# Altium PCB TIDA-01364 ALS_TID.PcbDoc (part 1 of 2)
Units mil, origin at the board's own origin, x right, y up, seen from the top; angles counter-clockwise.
Board outline 5000 x 4000 mil, 4 copper layers (Layer 1 - Top Layer, Layer 2 - GND, Layer 3 - PWR, Layer 4 - Bottom Layer), stack 61.434 mil thick; 133 components, 87 nets, 390 pads, 185 vias.
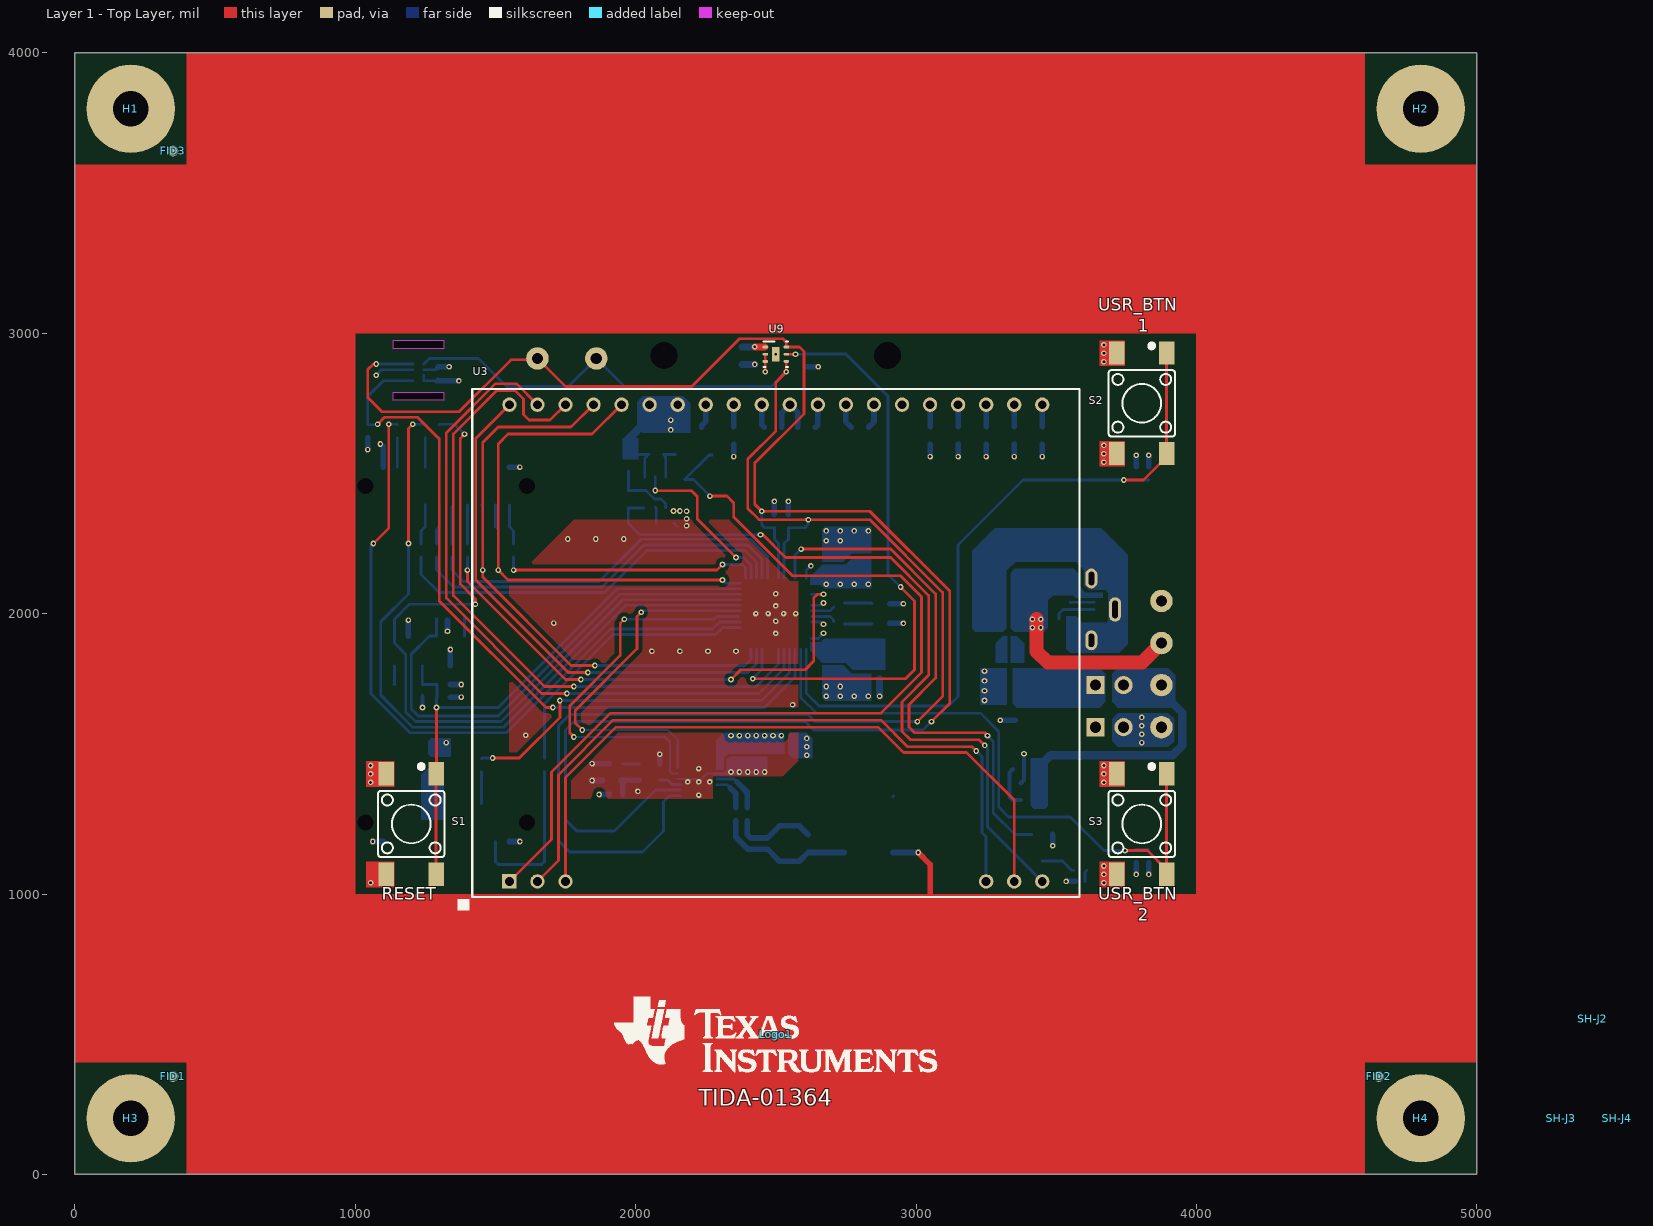
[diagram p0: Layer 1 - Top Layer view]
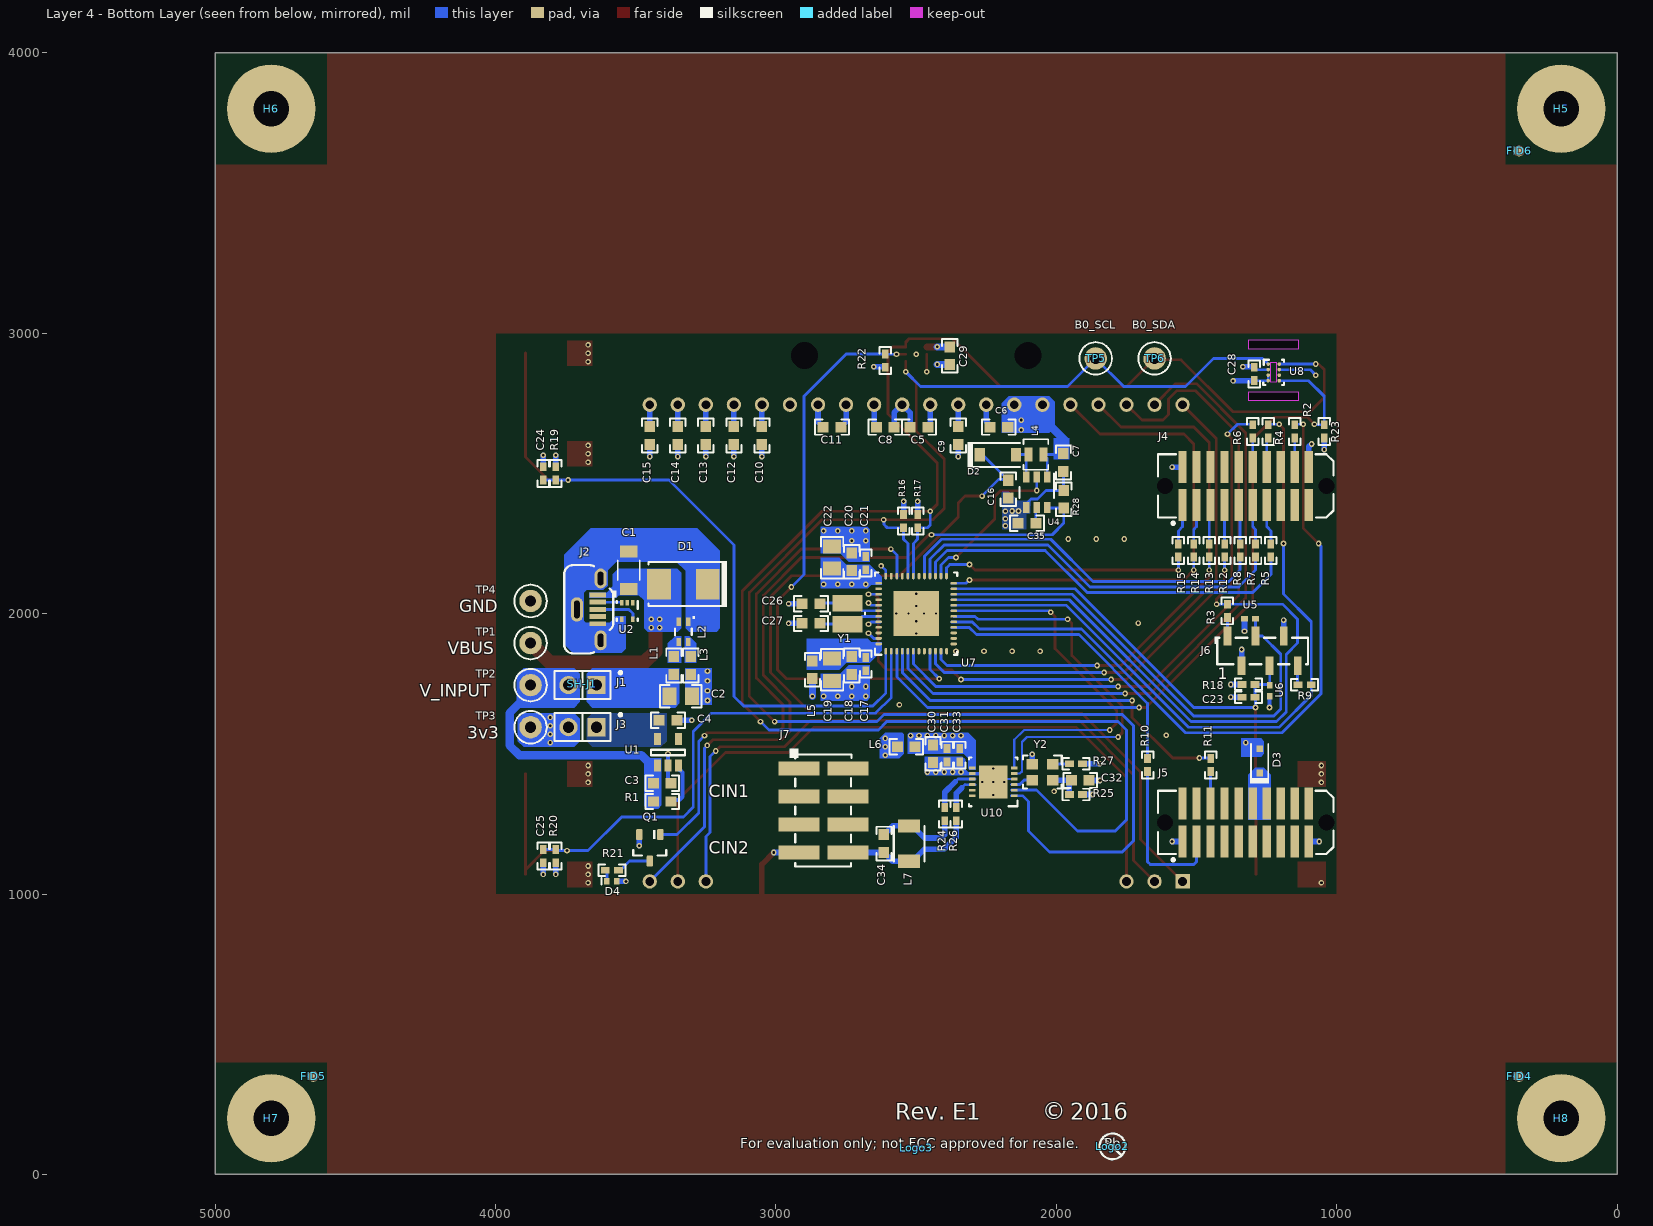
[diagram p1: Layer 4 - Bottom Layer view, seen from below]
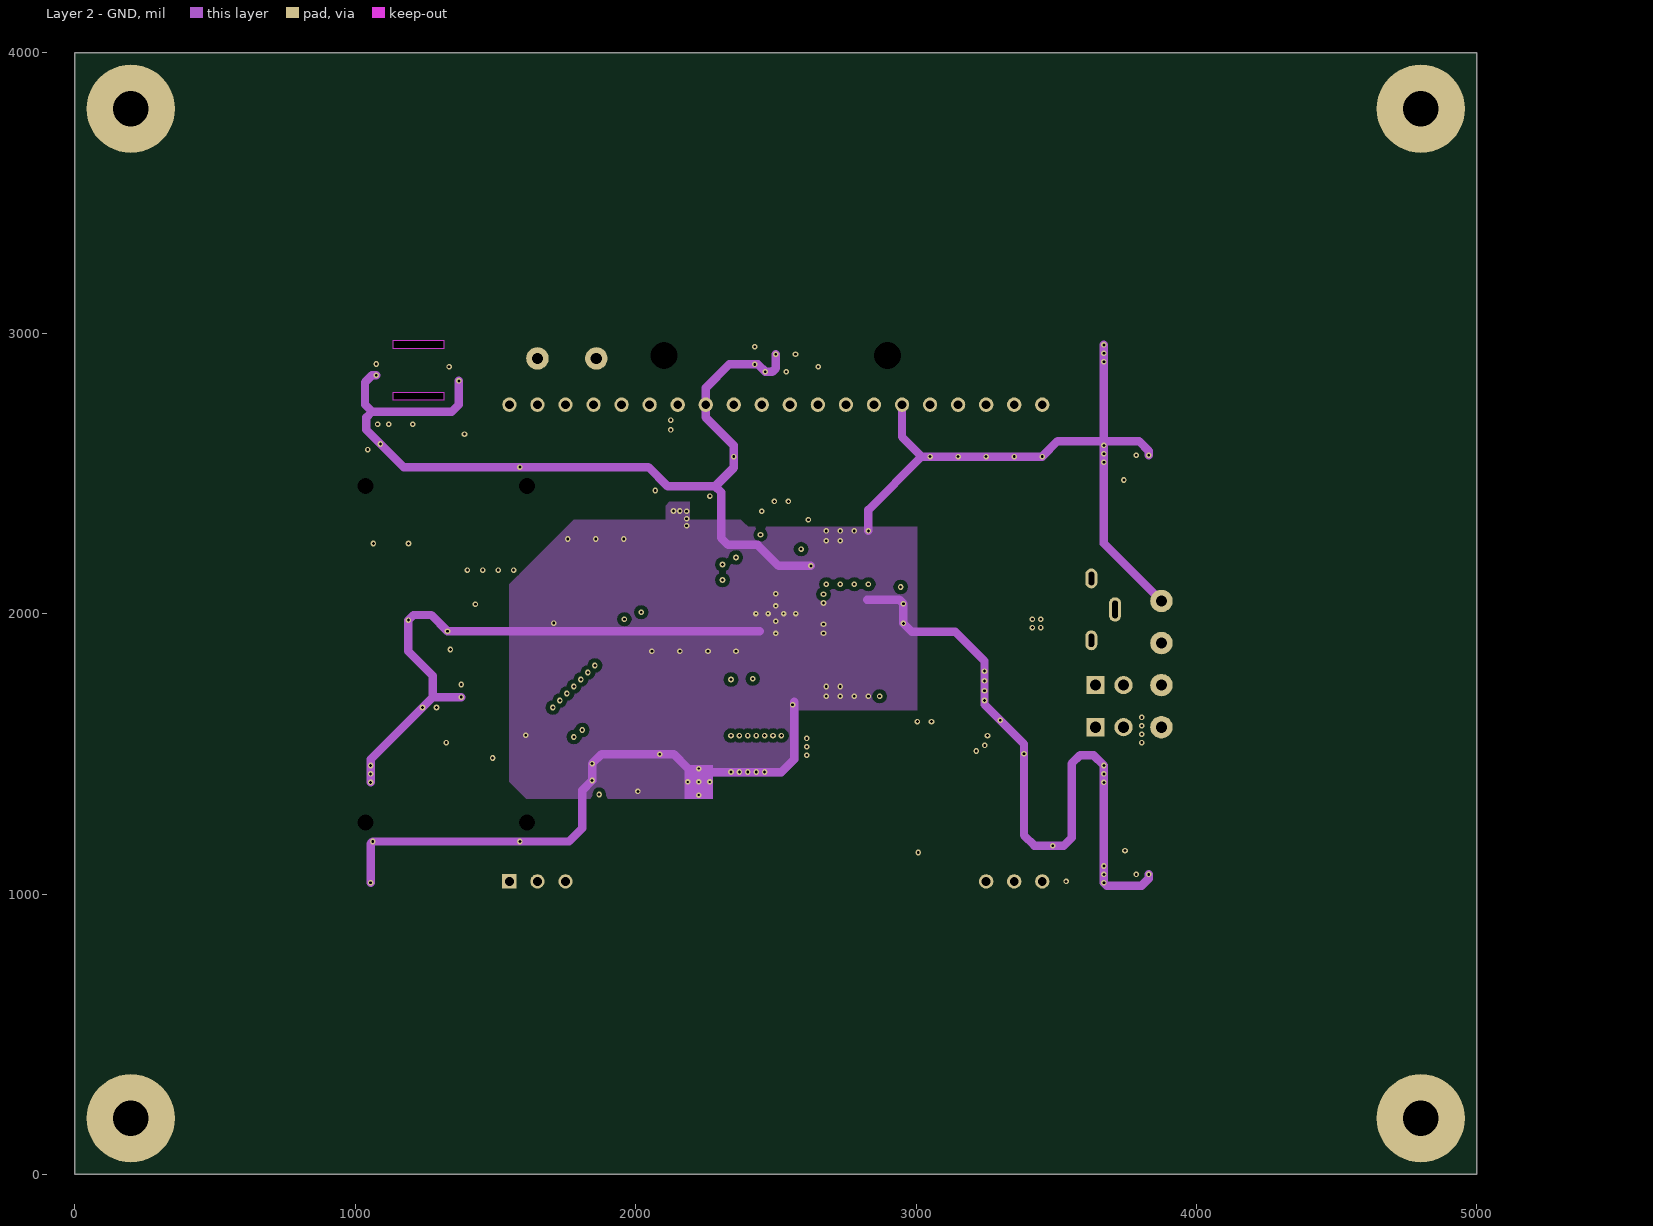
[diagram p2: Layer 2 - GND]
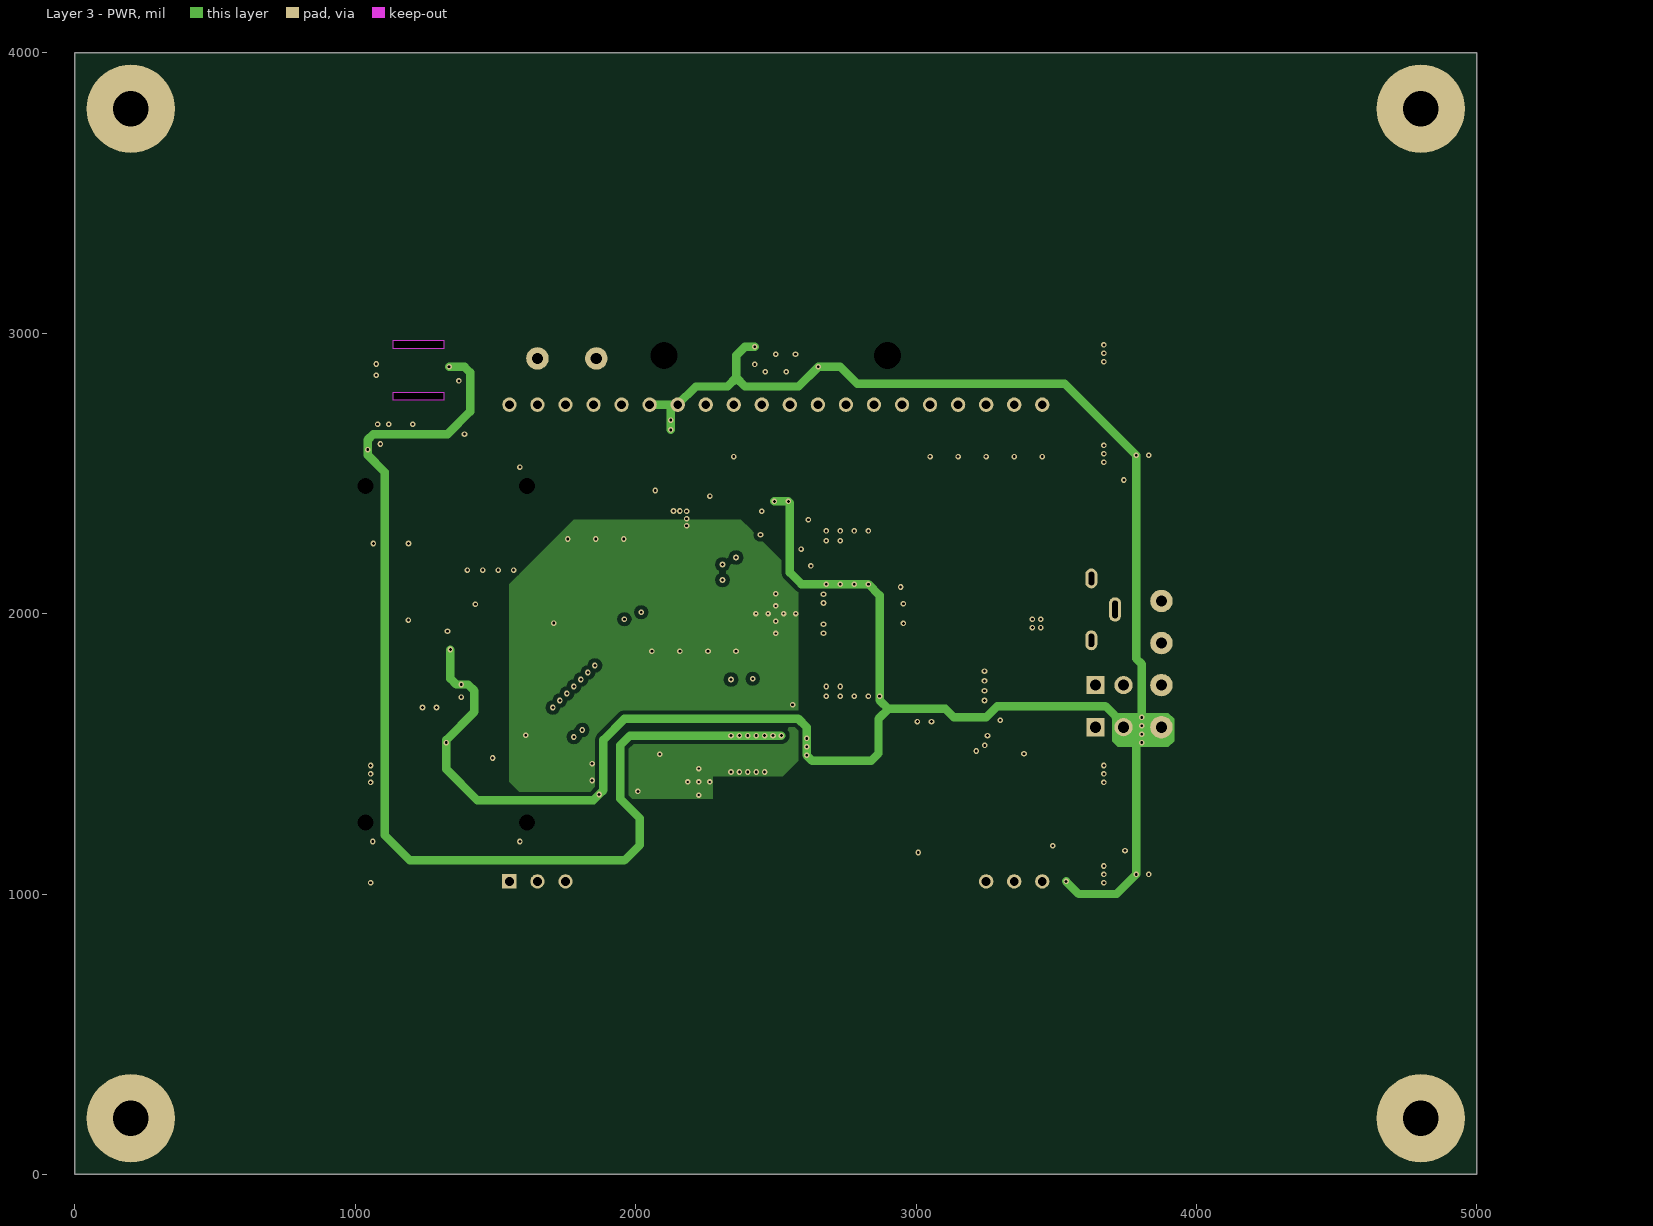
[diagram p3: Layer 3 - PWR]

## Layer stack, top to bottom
Top Solder: solder mask 0.4, Solder Resist, Dk 3.5
Layer 1 - Top Layer: signal copper 1.4
Dielectric1: prepreg 5, 370HR, Dk 4.2
Layer 2 - GND: signal copper 1.417
Dielectric 3: core 45.8, 370HR, Dk 4.2
Layer 3 - PWR: signal copper 1.417
Dielectric 2: prepreg 5, 370HR, Dk 4.2
Layer 4 - Bottom Layer: signal copper 1.4
Bottom Solder: solder mask 0.4, Solder Resist, Dk 3.5

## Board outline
0,0 5000,0 5000,4000 0,4000
cut-out: 1315,2975 1315,2945 1135,2945 1135,2975
cut-out: 1315,2790 1315,2760 1135,2760 1135,2790

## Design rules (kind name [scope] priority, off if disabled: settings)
AcuteAngle [All] p1: minimum=4.50000000000000E+0001 checktracksonly=FALSE
AssemblyTestPointUsage [All] p1: valid=2
Clearance Clearance_U4 [InComponent('U4')] p1: gap=4.6
Clearance Clearance_U8 [InComponent('U8')] p2: gap=3
Clearance Clearance_Keepouts [((IsTrack Or IsArc) And Not InPoly) And IsFree and IsKeepOut vs ((IsTrack Or IsArc) And Not InPoly) And IsFree and IsKeepOut] p3: gap=0
Clearance Clearance_BoardEdge_MountingHoles [OnCopper and InComponentClass('Mounting Holes') vs IsKeepOut] p4: gap=40
Clearance Clearance_BoardEdge_Poly [OnCopper and InPoly vs IsKeepOut] p5: gap=15
Clearance Clearance_BoardEdge [OnCopper and Not InComponentClass('Logo') and not InComponentClass('FiducialMark') and not InRegion(1000,500,4000,800) and Not IsKeepout vs IsKeepOut] p6 off: gap=75
Clearance Clearance_Poly [InPolygon] p7: gap=15
Clearance [All] p8: gap=6
ComponentClearance ComponentClearance_MountingHoles_FiducialMarks [InComponentClass('Mounting Holes') vs InComponentClass('FiducialMark')] p1 off: gap=50 collisioncheckmode=3 verticalgap=10 showdistances=FALSE
ComponentClearance ComponentClearance_Shunt [InComponentClass('Header') vs InComponentClass('Shunt')] p2 off: gap=0 collisioncheckmode=3 verticalgap=0 showdistances=FALSE
ComponentClearance ComponentClearance_Logo [InComponentClass('Logo')] p3 off: gap=50 collisioncheckmode=3 verticalgap=10 showdistances=FALSE
ComponentClearance ComponentClearance_ScrewToNut [(HasFootprint('NY PMS 440 0025 PH')) vs (HasFootprint('Keystone_1902C'))] p4 off: gap=5 collisioncheckmode=3 verticalgap=10 showdistances=FALSE
ComponentClearance ComponentClearance_MountingHoles [InComponentClass('Mounting Holes')] p5 off: gap=250 collisioncheckmode=3 verticalgap=100000 showdistances=FALSE
ComponentClearance ComponentClearance_SmallPassives [HasFootprint('0201*') or HasFootprint('0402*') or HasFootprint('0508') or HasFootprint('0603*') or HasFootprint('0612') or HasFootprint('0805*') or HasFootprint('0815*') or HasFootprint('0830*') or HasFootprint('1206*') or HasFootprint('1210*') or HasFootprint('1808*') or HasFootprint('1812*') or HasFootprint('1825*') or HasFootprint('2010*') or HasFootprint('2220*') or HasFootprint('2225*') or HasFootprint('2512*') or HasFootprint('2728*') or HasFootprint('3518*') vs HasFootprint('0201*') or HasFootprint('0402*') or HasFootprint('0508') or HasFootprint('0603*') or HasFootprint('0612') or HasFootprint('0805*') or HasFootprint('0815*') or HasFootprint('0830*') or HasFootprint('1206*') or HasFootprint('1210*') or HasFootprint('1808*') or HasFootprint('1812*') or HasFootprint('1825*') or HasFootprint('2010*') or HasFootprint('2220*') or HasFootprint('2225*') or HasFootprint('2512*') or HasFootprint('2728*') or HasFootprint('3518*')] p6 off: gap=20 collisioncheckmode=3 verticalgap=10 showdistances=FALSE
ComponentClearance ComponentClearance_THtoSMT [IsThruComponent vs IsSMTComponent] p7 off: gap=100 collisioncheckmode=3 verticalgap=30 showdistances=FALSE
ComponentClearance ComponentClearance_THtoTH [IsThruComponent vs IsThruComponent] p8 off: gap=118.11 collisioncheckmode=3 verticalgap=30 showdistances=FALSE
ComponentClearance [All] p9 off: gap=40 collisioncheckmode=3 verticalgap=10 showdistances=FALSE
DiffPairsRouting [All] p1: maxlimit=100 minlimit=10 mostfreqgap=10 toplayer_minwidth=15 toplayer_maxwidth=15 toplayer_prefwidth=15 midlayer1_minwidth=15 midlayer1_maxwidth=15 midlayer1_prefwidth=15 midlayer2_minwidth=15 midlayer2_maxwidth=15 midlayer2_prefwidth=15 bottomlayer_minwidth=15 bottomlayer_maxwidth=15 bottomlayer_prefwidth=15 maxuncoupledlength=1000
FabricationTestPointUsage TestPointUsage [All] p1: valid=2 allowmultiple=FALSE
FabricationTestpoint Testpoint [All] p1: side=3 testpointundercomponent=TRUE minsize=40 maxsize=100 preferedsize=60 minholesize=0 maxholesize=40 preferedholesize=32 testpointgrid=1 allowsidetop=TRUE allowsidebottom=TRUE usegrid=TRUE gridtolerance=0.01
FanoutControl Fanout_LCC [IsLCC] p1: bgadir=Out bgaviamode=Centered fanoutstyle=Auto fanoutdirection=Alternating viagrid=1 // Fanout_LCC (Default Rule)
FanoutControl Fanout_BGA [IsBGA] p2: bgadir=Out bgaviamode=Centered fanoutstyle=Auto fanoutdirection=Alternating viagrid=1 // Fanout_BGA (Default Rule)
FanoutControl Fanout_Default [All] p4: bgadir=Out bgaviamode=Centered fanoutstyle=Auto fanoutdirection=Alternating viagrid=1 // Fanout_Default (Default Rule)
FanoutControl Fanout_Small [(CompPinCount < 5)] p5: bgadir=Out bgaviamode=Centered fanoutstyle=Auto fanoutdirection=OutThenIn viagrid=1 // Fanout_Small (Default Rule)
Height [All] p1: minheight=0 maxheight=1005 prefheight=500
HoleSize [All] p1: absolutevalues=TRUE maxlimit=251 minlimit=7 maxpercent=80.000 minpercent=20.000
MinimumAnnularRing MinimumAnnularRing_ThermalPadVias [IsVia and InAnyComponent] p1: minimumring=5.91
MinimumAnnularRing [All] p2: minimumring=5
MinimumSolderMaskSliver MinimumSolderMaskSliver_Logo [InComponentClass('Logo') vs InComponentClass('Logo')] p1: minsoldermaskwidth=0.7
MinimumSolderMaskSliver [All] p2: minsoldermaskwidth=3.94
PlaneConnect [All] p1: planeconnectstyle=Relief reliefexpansion=10 reliefentries=4 reliefconductorwidth=10 reliefairgap=10
PolygonConnect [All] p1: connectstyle=Direct reliefconductorwidth=10 reliefentries=4 polygonreliefangle="90 Angle" airgapwidth=10
RoutingVias ThermalPadVias [IsVia and InAnyComponent] p1: holewidth=7.87 width=19.68 viastyle="Through Hole" minholewidth=7.87 minwidth=19.68 maxholewidth=12.99 maxwidth=23.62
RoutingVias [All] p2: holewidth=16 width=34 viastyle="Through Hole" minholewidth=7.87 minwidth=20 maxholewidth=40 maxwidth=65
SilkToBoardRegionClearance [Not ((IsComment or IsDesignator) And (Hide <> 'False')) and not InRegion(1000,500,4000,800)] p1:
SilkToSilkClearance SilkToSilkClearance_Pb-FreeLogo [(HasFootprint('Pb-Free_Overlay_Medium') OR HasFootprint('Pb-Free_Overlay_Small')) vs (HasFootprint('Pb-Free_Overlay_Medium') OR HasFootprint('Pb-Free_Overlay_Small'))] p1: silktosilkclearance=0
SilkToSilkClearance [All] p2: silktosilkclearance=5
SilkToSolderMaskClearance "Silk to Solder Mask Opening" [All] p1 off: minsilkscreentomaskgap=1 clearancetoexposedcopper=FALSE
SolderMaskExpansion [All] p1: expansion=1.97
Width "Schematic Width Constraint_5" [InNet('VBUS')] p1: maxlimit=100 minlimit=5 preferedwidth=25
Width "Schematic Width Constraint_4" [InNet('V_INPUT')] p2: maxlimit=100 minlimit=5 preferedwidth=25
Width "Schematic Width Constraint_3" [InNet('NetC2_1')] p3: maxlimit=100 minlimit=5 preferedwidth=25
Width "Schematic Width Constraint_2" [InNet('NetC4_1')] p4: maxlimit=100 minlimit=5 preferedwidth=25
Width "Schematic Width Constraint_1" [InNet('NetL1_1')] p5: maxlimit=100 minlimit=5 preferedwidth=25
Width "Schematic Width Constraint" [InNet('3P3V')] p6: maxlimit=100 minlimit=5 preferedwidth=25
Width [All] p7: maxlimit=100 minlimit=4 preferedwidth=10 checkconnectedcopper=TRUE
14 further rules are at their usual default settings.

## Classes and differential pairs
component class "Mounting Holes": H1 H2 H3 H4
component class Logo: Logo1
component class "TIDA-01364 ALS_TID_Hardware": FID1 FID2 FID3 FID4 FID5 FID6 H1 H2 H3 H4 H5 H6 H7 H8 Logo1 Logo2 Logo3 ZZ1 ZZ2 ZZ3 ZZ4 ZZ5 ZZ6 ZZ7 ZZ8 ZZ9
component class FiducialMark: FID1 FID2 FID3 FID4 FID5 FID6
component class AssemblyNote: ZZ1 ZZ2 ZZ3 ZZ5 ZZ6 ZZ7 ZZ8 ZZ9
component class Header: J1 J3 J7
component class "TIDA-01364 ALS_Sheet1": C1 C2 C3 C4 C5 C6 C7 C8 C9 C10 C11 C12 C13 C14 C15 C16 C35 D1 D2 J1 J2 J3 L1 L2 L3 L4 R1 R28 SH-J1 SH-J2 TP1 TP2 TP3 TP4 U1 U2 U3 U4
component class "TIDA-01364 ALS_Sheet2": C17 C18 C19 C20 C21 C22 C23 C24 C25 C26 C27 D3 D4 J4 J5 J6 L5 Q1 R2 R3 R4 R5 R6 R7 R8 R9 R10 R11 R12 R13 R14 R15 R16 R17 R18 R19 R20 R21 S1 S2 S3 U5 U6 U7 Y1
component class "TIDA-01364 ALS_Sheet3": C28 C29 C30 C31 C32 C33 C34 J7 L6 L7 R22 R23 R24 R25 R26 R27 SH-J3 SH-J4 TP5 TP6 U8 U9 U10 Y2
component class Shunt: SH-J1 SH-J2 SH-J3 SH-J4

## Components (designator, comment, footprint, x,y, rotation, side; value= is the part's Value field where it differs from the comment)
C1 "202R18W102KV4E" 1206_190 3525,2155 r90 bottom
C2 "08055C103JAT2A" 0805_HV 3340,1705 r180 bottom
C3 "C1608X7R1C105K" 0603 3405,1395 r180 bottom
C4 "C1608X7R1C105K" 0603 3385,1620 r180 bottom
C5 "C1608X7R1C105K" 0603 2490,2665 r0 bottom
C6 "C1608X7R1C105K" 0603 2205,2665 r0 bottom
C7 "GRM188R61A475ME15" 0603 1975,2539 r270 bottom
C8 "C1608X7R1C105K" 0603 2610,2665 r0 bottom
C9 "C1608X7R1C105K" 0603 2350,2635 r270 bottom
C10 "C1608X7R1C105K" 0603 3050,2635 r270 bottom
C11 "C1608X7R1C105K" 0603 2800,2665 r0 bottom
C12 "C1608X7R1C105K" 0603 3150,2635 r270 bottom
C13 "C1608X7R1C105K" 0603 3250,2635 r270 bottom
C14 "C1608X7R1C105K" 0603 3350,2635 r270 bottom
C15 "C1608X7R1C105K" 0603 3450,2635 r270 bottom
C16 "GRM188R61E105KA12D" 0603 2172,2444 r270 bottom
C17 "GRM155R71C104KA88D" 0402 2680,1820 r90 bottom
C18 "C1608X7R1C105K" 0603 2730,1815 r90 bottom
C19 "C2012X7R0J106M125AB" 0805_HV 2800,1800 r270 bottom
C20 "C1608X7R1C105K" 0603 2730,2185 r270 bottom
C21 "GRM155R71C104KA88D" 0402 2680,2180 r270 bottom
C22 "C2012X7R0J106M125AB" 0805_HV 2800,2200 r90 bottom
C23 "CGA2B2X7R1H222K050BA" 0402 1315,1702.3 r180 bottom
C24 "CGA2B2X7R1H222K050BA" 0402 3830,2500 r270 bottom
C25 "CGA2B2X7R1H222K050BA" 0402 3830,1135 r90 bottom
C26 "GRM1885C2A180JA01D" 0603 2875,2035 r0 bottom
C27 "GRM1885C2A180JA01D" 0603 2875,1965 r0 bottom
C28 "GRM155R71C104KA88D" 0402 1295,2855 r90 bottom
C29 "06033C104JAT2A" 0603 2380,2920 r270 bottom
C30 "C1608X7R1C105K" 0603 2440,1500 r270 bottom
C31 "GRM155R71C104KA88D" 0402 2390,1495 r90 bottom
C32 "GRM188R71E103KA01D" 0603 1915,1405 r180 bottom
C33 "GRM155R71C103KA01D" 0402 2345,1495 r270 bottom
C34 "GRM1885C2A330JA01D" 0603 2615,1180 r270 bottom
C35 "GRM188R61A224KA01D" 0603 2105,2322 r0 bottom
D1 "SMBJ6.0CA" SMB 3330,2105 r0 bottom
D2 "MBR0540T1G" SOD-123 2209,2566 r180 bottom
D3 "1SS315TPH3F" sod-323 1275,1475 r90 bottom
D4 "SML-P12PTT86" SML-P1_GREEN 3585,1045 r180 bottom
FID1 "Fiducial" Fiducial10-20 350,350 r0 top
FID2 "Fiducial" Fiducial10-20 4650,350 r0 top
FID3 "Fiducial" Fiducial10-20 350,3650 r0 top
FID4 "Fiducial" Fiducial10-20 350,350 r0 bottom
FID5 "Fiducial" Fiducial10-20 4650,350 r0 bottom
FID6 "Fiducial" Fiducial10-20 350,3650 r0 bottom
H1 "NY PMS 440 0025 PH" "NY PMS 440 0025 PH" 200,3800 r0 top
H2 "NY PMS 440 0025 PH" "NY PMS 440 0025 PH" 4800,3800 r0 top
H3 "NY PMS 440 0025 PH" "NY PMS 440 0025 PH" 200,200 r0 top
H4 "NY PMS 440 0025 PH" "NY PMS 440 0025 PH" 4800,200 r0 top
H5 "1902E" Keystone_1902E 200,3800 r180 bottom
H6 "1902E" Keystone_1902E 4800,3800 r180 bottom
H7 "1902E" Keystone_1902E 4800,200 r180 bottom
H8 "1902E" Keystone_1902E 200,200 r180 bottom
J1 "90120-0122" CONN_90120-0122 3690,1745 r0 bottom
J2 "1051330001" Molex_1051330001 3635,2015 r270 bottom
J3 "90120-0122" CONN_90120-0122 3690,1595 r0 bottom
J4 "TFM-110-02-L-D-A" Samtec_TFM-110-02-L-D-A 1325,2455 r180 bottom locked
J5 "TFM-110-02-L-D-A" Samtec_TFM-110-02-L-D-A 1325,1255 r180 bottom locked
J6 "LPPB061NFSC-RC" Sullins_LPPB061NFSC-RC 1264.69,1866.81 r180 bottom
J7 "0015910080" Molex_0015910080 2830.5,1298 r270 bottom
L1 "BLM18SG331TN1D" 0603 3364,1815 r270 bottom
L2 "SRF2012-361YA" SRF2012A 3330,1935 r270 bottom
L3 "BLM18SG331TN1D" 0603 3304,1815 r270 bottom
L4 "VLF252015MT-100M" IND_VLF252015 2072.87,2567.25 r0 bottom
L5 "BLM18SG331TN1D" 0603 2870,1800 r90 bottom
L6 "BLM18SG331TN1D" 0603 2535,1525 r0 bottom
L7 "CMH322522-180KL" CMH322522 2525,1180 r90 bottom
Logo1 "Texas Instruments" TI_Stacked_Overlay_Medium 2500,500 r0 top
Logo2 "Pb-Free Symbol" Pb-Free_Overlay_Small 1800,100 r180 bottom
Logo3 "FCC disclaimer" FCC_disclaimer 2500,95 r180 bottom
Q1 "BSS138" SOT-23 3450,1165 r270 bottom
R1 "CRCW06030000Z0EA" 0603 3405,1330 r180 bottom
R2 "CRCW04020000Z0ED" 0402 1150,2650 r90 bottom
R3 "CRCW04020000Z0ED" 0402 1390,2010 r270 bottom
R4 "CRCW04020000Z0ED" 0402 1245,2650 r270 bottom
R5 "CRCW04020000Z0ED" 0402 1235,2225 r270 bottom
R6 "CRCW04020000Z0ED" 0402 1300,2650 r270 bottom
R7 "CRCW04020000Z0ED" 0402 1290,2225 r90 bottom
R8 "CRCW04020000Z0ED" 0402 1345,2225 r90 bottom
R9 "CRCW04020000Z0ED" 0402 1114.69,1746.81 r0 bottom
R10 "CRCW04020000Z0ED" 0402 1675,1460 r270 bottom
R11 "CRCW04020000Z0ED" 0402 1450,1460 r90 bottom
R12 "CRCW04020000Z0ED" 0402 1400,2225 r270 bottom
R13 "CRCW04020000Z0ED" 0402 1455,2225 r270 bottom
R14 "CRCW04020000Z0ED" 0402 1510,2225 r270 bottom
R15 "CRCW04020000Z0ED" 0402 1565,2225 r90 bottom
R16 "CRCW04024K99FKED" 0402 2545,2330 r90 bottom
R17 "CRCW04024K99FKED" 0402 2495,2330 r90 bottom
R18 "CRCW040247K5FKED" 0402 1315,1747.3 r0 bottom
R19 "CRCW040247K5FKED" 0402 3785,2500 r90 bottom
R20 "CRCW040247K5FKED" 0402 3785,1135 r270 bottom
R21 "CRCW0402221RFKED" 0402 3585,1085 r0 bottom
R22 "CRCW040210K0JNED" 0402 2610,2901.99 r270 bottom
R23 "CRCW04024K99FKED" 0402 1045,2650 r270 bottom
R24 "CRCW04020000Z0ED" 0402 2398,1285 r90 bottom
R25 "CRCW04020000Z0ED" 0402 1930,1355 r180 bottom
R26 "CRCW04020000Z0ED" 0402 2357,1285 r90 bottom
R27 "CRCW04020000Z0ED" 0402 1930,1465 r180 bottom
R28 "CRCW06038R06FKEA" 0603 1974,2408 r270 bottom
S1 "4-1437565-1" SW_FSM4JSMA 1200,1250 r0 top
S2 "4-1437565-1" SW_FSM4JSMA 3805,2750 r0 top
S3 "4-1437565-1" SW_FSM4JSMA 3805,1250 r0 top
SH-J1 "2SN-BK-G" 2SN-BK-G#1 3690,1750 r180 bottom
SH-J2 "2SN-BK-G" 2SN-BK-G#2 5414,555 r90 top
SH-J3 "2SN-BK-G" 2SN-BK-G#2 5300,200 r90 top
SH-J4 "2SN-BK-G" 2SN-BK-G#2 5500,200 r90 top
TP1 "5000" Keystone5000 3875,1895 r180 bottom
TP2 "5000" Keystone5000 3875,1745 r180 bottom
TP3 "5000" Keystone5000 3875,1595 r180 bottom
TP4 "5001" Keystone5001 3875,2045 r180 bottom
TP5 "5004" Keystone5004 1860,2910 r90 bottom
TP6 "5004" Keystone5004 1650,2910 r90 bottom
U1 "TLV71333PDBVR" DBV0005A_N 3385,1505 r90 bottom
U2 "TPD2E2U06DRLR" DRL0005A 3530,2010 r270 bottom
U3 "EA DOGM128W-6" "LCD-MODULE_EA DOGM128W-6" 2500,1895 r0 top locked
U4 "TPS61165DBVR" DBV0006A_N 2070.06,2433 r270 bottom
U5 "TPD1E10B06DPYR" DPY0002A 1309.69,1981.81 r0 bottom
U6 "TPD1E10B06DPYR" DPY0002A 1240,1725 r270 bottom
U7 "MSP430FR5969IRGZ" RGZ0048B 2500,2000 r90 bottom locked
U8 "HDC1010YPAR" YPA0008AGAE 1225,2860 r180 bottom
U9 "OPT3001DNPR" DNP0006A 2500,2925 r0 top
U10 "FDC2212DNTR" DNT0012B 2225,1400 r0 bottom
Y1 "NX3225GD-8MHZ-STD-CRA-3" NDK_NX3225GD 2745,2000 r270 bottom
Y2 "KC2520B40.0000C10E00" AVX_KC2520B 2050,1435 r270 bottom
ZZ1 "These assemblies are ESD sensitive, ESD precautions shall be observed." AssemblyNote 0,5000 r0 top
ZZ2 "These assemblies must be clean and free from flux and all contaminants. Use of no clean flux is not acceptable." AssemblyNote 0,4900 r0 top
ZZ3 "These assemblies must comply with workmanship standards IPC-A-610 Class 2, unless otherwise specified." AssemblyNote 0,4800 r0 top
ZZ4 "Place SH-J1 on J1 and SH-J2 on J3 (pins 1 -2) and SH-J3 to SH-J4 on J7, SH-J3 (pins 1-2)" AssemblyNote 0,4700 r0 top
ZZ5 "Component BL1 must be assembled to U3 Before U3 is attached to the board." AssemblyNote 0,4600 r0 top
ZZ6 "Remove protective coverings from BL1 and U3" AssemblyNote 0,4500 r0 top
ZZ7 "Slide pins of U3 into holes of BL1. BL1 must lie flat on the back of U3" AssemblyNote 0,4400 r0 top
ZZ8 "Solder U3 - BL1 assembly to the board." AssemblyNote 0,4300 r0 top
ZZ9 "Solder Pins 1, 2, 3, 18, 19, and 20 of U3 to BL1 from the top to insure electrical continuity." AssemblyNote 0,4200 r0 top

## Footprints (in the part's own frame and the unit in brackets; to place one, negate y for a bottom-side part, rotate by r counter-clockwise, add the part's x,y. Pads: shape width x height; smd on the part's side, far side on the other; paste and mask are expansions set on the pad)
2SN-BK-G#1 [mil] "Samtec STEP model"
  round 1 on Mech4: 0(0,0)
  body extent -78,-39 79,39, height 188
2SN-BK-G#2 [mil] "Samtec STEP model"
  round 1 on Mech3: 0(0,0)
  body extent -78,-39 79,39, height 188
0402 [mm] "0402 from SM-752 data"
  rect 0.8x0.6 smd: 1(-0.6,0) 2(0.6,0)
  silkscreen extent -1.22,-0.52 1.22,0.52, body extent -0.55,-0.3 0.55,0.3, height 0.6
0603 [mm] "0603 from SM-752 data"
  rect 1x0.95 smd: 1(-0.8,0) 2(0.8,0)
  silkscreen extent -1.52,-0.69 1.52,0.69, body extent -0.87,-0.47 0.87,0.47, height 0.85
0805_HV [mil] "0805 with 30mil clearance between pads"
  rect 50x63 smd: 1(-40,0) 2(40,0)
  silkscreen extent -74,-40 74,40, body extent -43,-29 43,29, height 43
1206_190 [mm] "1206_190"
  rect 1.1x1.6 smd: 1(-1.7,0) 2(1.7,0)
  silkscreen extent -0.9,-1 0.9,1, body extent -1.75,-0.95 1.75,0.95, height 1.9
AssemblyNote [mil] "Assembly Note"
AVX_KC2520B [mm] "SMD, 4-Leads, Body 2.5x2mm"
  rect 0.95x1.05 smd: 1(-0.725,0.925) 2(-0.725,-0.925) 3(0.725,-0.925) 4(0.725,0.925)
  silkscreen extent -1.5,-1.75 1.5,1.75, body extent -1.05,-1.3 1.05,1.3, height 0.81
CMH322522 [mm] "Bourns"
  rect 1.2x2 smd: 1(-1.6,0) 2(1.6,0)
  silkscreen extent -1.6,-1.4 1.6,1.4, body extent -1.7,-1.35 1.7,1.35, height 2.4
CONN_90120-0122 [mm] "Molex"
  rect 1.65x1.65 hole 1.016 mask+0: 1(-1.27,0)
  round 1.65 hole 1.016 mask+0: 2(1.27,0)
  silkscreen extent -3.56,-1.27 2.54,1.27, body extent -2.54,-1.27 2.54,1.27, height 9.29
DBV0005A_N [mm] "SOT23, 5-Leads, Body 2.9x1.6mm, Pitch 0.95mm, Lead Span 2.8mm, IPC Medium Density"
  rect 1.1x0.65 smd: 1(-1.2,0.95) 2(-1.2,0) 3(-1.2,-0.95) 4(1.2,-0.95) 5(1.2,0.95)
  silkscreen extent -0.25,-1.55 0.25,1.55, body extent -1.42,-1.46 1.42,1.46, height 1.08
DBV0006A_N [mm] "SOT23, 6-Leads, Body 2.9x1.6mm, Pitch 0.95mm, Lead Span 2.8mm, IPC Medium Density"
  rrect17% 1x0.6 smd: 1(-1.375,0.95) 2(-1.375,0) 3(-1.375,-0.95) 4(1.375,-0.95) 5(1.375,0) 6(1.375,0.95)
  silkscreen extent -1.68,-1.55 0.5,1.55, body extent -1.42,-1.46 1.42,1.46, height 1.12
DNP0006A [mm] "DFN-6 2x2mm"
  oval 0.5x0.25 smd: 1(-0.95,0.65) 2(-0.95,0) 3(-0.95,-0.655) 4(0.95,-0.65) 5(0.95,0) 6(0.95,0.65)
  rect 0.65x1.35 smd paste-0.5: 7(0,0)
  silkscreen extent -1.12,-1.15 1.12,1.15, body extent -1.05,-1.05 1.05,1.05, height 0.66
DNT0012B [mm] "SON, 12-Leads, Body 4x4mm, Pitch 0.5mm"
  rrect40% 0.6x0.25 smd: 1(-1.9,1.25) 2(-1.9,0.75) 3(-1.9,0.25) 4(-1.9,-0.25) 5(-1.9,-0.75) 6(-1.9,-1.25) 7(1.9,-1.25) 8(1.9,-0.75) 9(1.9,-0.25) 10(1.9,0.25) 11(1.9,0.75) 12(1.9,1.25)
  rrect4% 2.6x3 smd paste-1.3: 13(0,0)
  silkscreen extent -2.2,-2.2 2.2,2.2, body extent -2.05,-2.05 2.05,2.05, height 0.81
DPY0002A [mm] "R-PX2SON-N2"
  rect 0.6x0.5 smd: 1(-0.5,0) 2(0.5,0)
  body extent -0.55,-0.35 0.55,0.35, height 0.4
DRL0005A [mm] "SOTFL, 5-Flat Leads, Body 1.2x1.6x0.6mm, Pitch 0.5mm, TI recommended"
  rect 0.5x0.3 smd: 1(-0.75,0.5) 2(-0.75,0) 3(-0.75,-0.5) 4(0.75,-0.5) 5(0.75,0.5)
  silkscreen extent -0.9,-0.95 0.9,0.95, body extent -0.85,-0.85 0.85,0.85, height 0.62
FCC_disclaimer [mil]
Fiducial10-20 [mm]
  round 1 smd mask+0.5: 1(0,0)
IND_VLF252015 [mm] "TDK"
  rect 0.75x1.3 smd: 1(-0.675,0) 2(0.675,0)
  silkscreen extent -1.12,-1.38 1.12,1.38, body extent -1.1,-1.35 1.1,1.35, height 1.5
Keystone5000 [mil] "For Keystone 500x miniature loop terminals"
  round 80 hole 40: 1(0,0)
  silkscreen extent -58,-58 58,58, body extent -49,-49 49,49, height 182
Keystone5001 [mil] "For Keystone 500x miniature loop terminals"
  round 80 hole 40: 1(0,0)
  silkscreen extent -58,-58 58,58, body extent -49,-49 49,49, height 182
Keystone5004 [mil] "For Keystone 500x miniature loop terminals"
  round 80 hole 40: 1(0,0)
  silkscreen extent -58,-58 58,58, body extent -49,-49 49,49, height 182
Keystone_1902E [mil] "Hex Standoff, 4-40 threaded, nylon"
  round 1 on Mech4: 0(0,0)
  body extent -145,-126 146,126, height 1001
"LCD-MODULE_EA DOGM128W-6" [mm] "LCD-MODULE"
  rect 1.3x1.3 hole 0.8: 1(-24.13,-21.59)
  round 1.3 hole 0.8: 2(-21.59,-21.59) 3(-19.05,-21.59) 18(19.05,-21.59) 19(21.59,-21.59) 20(24.13,-21.59) 21(24.13,21.59) 22(21.59,21.59) 23(19.05,21.59) 24(16.51,21.59) 25(13.97,21.59) 26(11.43,21.59) 27(8.89,21.59) 28(6.35,21.59) 29(3.81,21.59) 30(1.27,21.59) 31(-1.27,21.59) 32(-3.81,21.59) 33(-6.35,21.59) 34(-8.89,21.59) 35(-11.43,21.59) 36(-13.97,21.59) 37(-16.51,21.59) 38(-19.05,21.59) 39(-21.59,21.59) 40(-24.13,21.59)
  silkscreen extent -28.8,-24.21 27.5,23, body extent -27.5,-23 27.5,23, height 7.31
Molex_0015910080 [mm] "MOLEX"
  rect 1.27x3.68 smd: 1(-3.81,-2.22) 2(-3.81,2.22) 3(-1.27,-2.22) 4(-1.27,2.22) 5(1.27,-2.22) 6(1.27,2.22) 7(3.81,-2.22) 8(3.81,2.22)
  silkscreen extent -5.62,-3.1 5.07,2.52, body extent -5.08,-3.49 5.08,3.49, height 9.64
Molex_1051330001 [mm] "Connector, Receptacle, USB TYPE B, Vertical, TH"
  rect 0.45x1.5 smd: 1(-1.3,0) 2(-0.65,0) 3(0,0) 4(0.65,0) 5(1.3,0)
  oval 1.8x1.1 hole 0.5 slot 1.2 at 0 deg: 6(-2.8,0.25) 7(2.8,0.25)
  oval 2.2x1.1 hole 0.5 slot 1.6 at 0 deg: 8(0,-1.9)
  silkscreen extent -4.01,-3.05 3.99,1.7, body extent -4.02,-3.05 4,1.4, height 7.46
NDK_NX3225GD [mm] "NDK"
  rect 1.5x2.7 smd: 1(-0.95,0) 2(0.95,0)
  silkscreen extent -0.13,-1.58 0.1,1.58, body extent -1.65,-1.3 1.65,1.3, height 1
"NY PMS 440 0025 PH" [mm] "4-40 nylon screw and mounting hole"
  round 8 hole 3.2: 1(0,0)
  body extent -3.3,-3.3 3.3,3.3, height 2.69
Pb-Free_Overlay_Small [mil]
  silkscreen extent -46,-46 46,46
RGZ0048B [mm] "QFN, 48-Leads, Body 7x7mm, Pitch 0.5mm, Thermal Pad 5.15x5.15mm, TI Recommended"
  oval 0.6x0.24 smd: 1(-3.4,2.75) 2(-3.4,2.25) 3(-3.4,1.75) 4(-3.4,1.25) 5(-3.4,0.75) 6(-3.4,0.25) 7(-3.4,-0.25) 8(-3.4,-0.75) 9(-3.4,-1.25) 10(-3.4,-1.75) 11(-3.4,-2.25) 12(-3.4,-2.75) 25(3.4,-2.75) 26(3.4,-2.25) 27(3.4,-1.75) 28(3.4,-1.25) 29(3.4,-0.75) 30(3.4,-0.25) 31(3.4,0.25) 32(3.4,0.75) 33(3.4,1.25) 34(3.4,1.75) 35(3.4,2.25) 36(3.4,2.75)
  oval 0.24x0.6 smd: 13(-2.75,-3.4) 14(-2.25,-3.4) 15(-1.75,-3.4) 16(-1.25,-3.4) 17(-0.75,-3.4) 18(-0.25,-3.4) 19(0.25,-3.4) 20(0.75,-3.4) 21(1.25,-3.4) 22(1.75,-3.4) 23(2.25,-3.4) 24(2.75,-3.4) 37(2.75,3.4) 38(2.25,3.4) 39(1.75,3.4) 40(1.25,3.4) 41(0.75,3.4) 42(0.25,3.4) 43(-0.25,3.4) 44(-0.75,3.4) 45(-1.25,3.4) 46(-1.75,3.4) 47(-2.25,3.4) 48(-2.75,3.4)
  rect 4.1x4.1 smd paste-2.575: 49(0,0)
  silkscreen extent -3.72,-3.72 3.72,3.72, body extent -3.57,-3.58 3.58,3.57, height 1.01
Samtec_TFM-110-02-L-D-A [mm] "Samtec"
  rect 0.74x2.92 smd paste+0: 1(-5.715,-1.715) 2(-5.715,1.715) 3(-4.445,-1.715) 4(-4.445,1.715) 5(-3.175,-1.715) 6(-3.175,1.715) 7(-1.905,-1.715) 8(-1.905,1.715) 9(-0.635,-1.715) 10(-0.635,1.715) 11(0.635,-1.715) 12(0.635,1.715) 13(1.905,-1.715) 14(1.905,1.715) 15(3.175,-1.715) 16(3.175,1.715) 17(4.445,-1.715) 18(4.445,1.715) 19(5.715,-1.715) 20(5.715,1.715)
  round 0.508 hole 1.45 unplated paste+0: MH1(-7.305,0) MH2(7.305,0)
  silkscreen extent -7.93,-3.49 7.95,2.87, body extent -7.93,-2.95 7.94,3.02, height 5.74
SMB [mil] "Molded Diode, 2-Leads, Body 5.4x3.6mm, IPC Medium Density, based on OnSemi component dimensions"
  rect 85x107.99 smd: 1(-87.01,0) 2(87.01,0)
  silkscreen extent -155,-82 125,82, body extent -106,-71 106,71, height 91
SML-P1_GREEN [mm] "ROHM"
  rect 0.5x0.6 smd: 1(-0.45,0) 2(0.45,0)
  silkscreen extent -0.95,-0.3 -0.95,0.3, body extent -0.53,-0.33 0.53,0.33, height 0.25
SOD-123 [mm] "On Semi recommended land pattern"
  rect 0.915x1.22 smd: 1(-1.637,0) 2(1.637,0)
  silkscreen extent -2.74,-1.17 2.03,1.17, body extent -1.93,-0.9 1.93,0.9, height 1.35
sod-323 [mm] "NXP recommended land pattern"
  rect 0.6x0.6 smd paste-0.05: 1(-1.1,0) 2(1.1,0)
  silkscreen extent -2.06,-0.86 1.53,0.86, body extent -1.3,-0.67 1.3,0.68, height 1.1
SOT-23 [mm] "SOT23, 3-Leads, Body 2.9x1.3mm, Pitch 0.95mm, Lead Span 2.5mm, IPC Medium Density"
  rrect50% 1x0.6 smd: 1(-1.2,0.95) 2(-1.2,-0.95) 3(1.2,0)
  silkscreen extent -1.62,-1.5 0.7,1.5, body extent -1.16,-1.45 1.21,1.45, height 1
SRF2012A [mm] "BOURNS"
  rect 0.75x0.4 smd: 1(-0.925,0.425) 2(0.925,0.425) 3(0.925,-0.425) 4(-0.925,-0.425)
  silkscreen extent -1.42,-0.75 0.3,1.05, body extent -1.1,-0.7 1.1,0.7, height 1.41
Sullins_LPPB061NFSC-RC [mm] "Receptacle, 1.27mm, 6x1, SMT"
  rect 0.7x1.7 smd: 1(-3.175,1.35) 2(-1.905,-1.35) 3(-0.635,1.35) 4(0.635,-1.35) 5(1.905,1.35) 6(3.175,-1.35)
  silkscreen extent -4.37,-1.2 4.11,1.3, body extent -4.11,-1.65 4.11,1.65, height 4.85
SW_FSM4JSMA [mm] "Alcoswitch"
  rect 1.4x2.1 smd: 1(2.25,4.55) 2(2.25,-4.55) 3(-2.25,4.55) 4(-2.25,-4.55)
  silkscreen extent -3,-3 3,5.4, body extent -3,-5 3,5, height 5.1
TI_Stacked_Overlay_Medium [mil]
  silkscreen extent -576,-136 576,134
YPA0008AGAE [mm] "BGA, 8-Leads, Body 2.04x1.59mm, Pitch 0.5mm"
  round 0.32 smd paste-0.12 mask+0.025: A1(-0.5,0.75) A2(0.5,0.75) B1(-0.5,0.25) B2(0.5,0.25) C1(-0.5,-0.25) C2(0.5,-0.25) D1(-0.5,-0.75) D2(0.5,-0.75)
  Layer 1 - Top Layer keep-out region: -0.25,0.9 0.25,0.9 0.25,-0.9 -0.25,-0.9
  silkscreen extent -0.94,-1.14 0.94,1.14, body extent -0.82,-1.04 0.81,1.04, height 0.68

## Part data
C1: "CAP, CERM, 1000 pF, 2000 V, +/- 10%, X7R, 1206_190"
C2: "CAP, CERM, 0.01 µF, 50 V, +/- 5%, X7R, 0805"
C3 C4: "CAP, CERM, 1 µF, 16 V, +/- 10%, X7R, 0603"
C5 C6 C8 C9 C10 C11 C12 C13 C14 C15 C18 C20 C30: "CAP, CERM, 1uF, 16V, +/-10%, X7R, 0603"
C7: "CAP, CERM, 4.7 µF, 10 V, +/- 20%, X5R, 0603"
C16: "CAP, CERM, 1 µF, 25 V, +/- 10%, X5R, 0603"
C17 C21 C28 C31: "CAP, CERM, 0.1uF, 16V, +/-10%, X7R, 0402"
C19 C22: "CAP, CERM, 10 µF, 6.3 V, +/- 20%, X7R, 0805"
C23 C24 C25: "CAP, CERM, 2200 pF, 50 V, +/- 10%, X7R, AEC-Q200 Grade 1, 0402"
C26 C27: "CAP, CERM, 18pF, 100V, +/-5%, C0G/NP0, 0603"
C29: "CAP, CERM, 0.1 µF, 25 V, +/- 5%, X7R, 0603"
C32: "CAP, CERM, 0.01 µF, 25 V, +/- 10%, X7R, 0603"
C33: "CAP, CERM, 0.01 µF, 16 V, +/- 10%, X7R, 0402"
C34: "CAP, CERM, 33 pF, 100 V, +/- 5%, C0G/NP0, 0603"
C35: "CAP, CERM, 0.22 µF, 10 V, +/- 10%, X5R, 0603"
D1: "Diode, TVS, Bi, 6 V, 600 W, SMB"
D2: "Diode, Schottky, 40 V, 0.5 A, SOD-123"
D3: "Diode, Schottky, 5V, 0.03A, SOD-323"
D4: "LED, Green, SMD"
FID1 FID2 FID3 FID4 FID5 FID6: "Fiducial mark.  There is nothing to buy or mount."
H1 H2 H3 H4: "Machine Screw, Round, #4-40 x 1/4, Nylon, Philips panhead"
H5 H6 H7 H8: "Standoff, Hex, 1\"L #4-40 Nylon"
J1 J3: "Header, 100mil, 2x1, Tin, TH"
J2: "Connector, Receptacle, USB TYPE B, Vertical, TH"
J4 J5: "Straight Low Profile Header, 10x2 Position,1.27 mm Pitch, SMT"
J6: "Receptacle, 1.27mm, 6x1, Gold, SMT"
J7: "Header, 100mil, 4x2, Gold, SMT"
L1 L3: "Ferrite Bead, 330 ohm @ 100 MHz, 1.5 A, 0603"
L2: "Inductor, Wirewound, Ferrite, , 0.3 A, 0.45 ohm, SMD"
L4: "Inductor, Shielded, Ferrite, 10uH, 0.47A, 0.24 ohm, SMD"
L5 L6: "1.5A Ferrite Bead, 330 ohm @ 100MHz, SMD"
L7: "Inductor, Shielded, Ferrite, 18 µH, 0.12 A, 3.3 ohm, SMD"
Logo1: library part TI_Logo, "Texas Instrument Corporate Signature"
Logo2: library part Pb-Free
Logo3: library part FCC_disclaimer, "FCC_disclaimer"
Q1: "MOSFET, N-CH, 50V, 0.22A, SOT-23"
R1: "RES, 0, 5%, 0.1 W, 0603"
R2 R3 R4 R5 R6 R7 R8 R9 R10 R11 R12 R13 R14 R15: "RES, 0 ohm, 5%, 0.063W, 0402"
R16 R17: "RES, 4.99k ohm, 1%, 0.063W, 0402"
R18 R19 R20: "RES, 47.5 k, 1%, 0.063 W, 0402"
R21: "RES, 221 ohm, 1%, 0.063W, 0402"
R22: "RES, 10 k, 5%, 0.063 W, 0402"
R23: "RES, 4.99 k, 1%, 0.063 W, 0402"
R24 R25 R26 R27: "RES, 0, 5%, 0.063 W, 0402"
R28: "RES, 8.06, 1%, 0.1 W, 0603"
S1 S2 S3: "Switch, Tactile, SPST-NO, 0.05A, 12V, SMT"
SH-J1 SH-J2 SH-J3 SH-J4: "Shunt, 2mm, Gold plated, Black"
TP1 TP2 TP3: "Test Point, Miniature, Red, TH"
TP4: "Test Point, Miniature, Black, TH"
TP5 TP6: "Test Point, Miniature, Yellow, TH"
U1: library part TLV71333PDBV, "Capacitor-Free, 150-mA, Low-Dropout Regulator with Foldback Current Limit for Portable Devices, DBV0005A"
U2: "DUAL CHANNEL HIGH SPEED ESD PROTECTION DEVICE, DRL0005A"
U3: "Module, 128x64-pixel graphics display"
U4: "High Brightness White LED Driver, 3 to 18 V, -40 to 85 degC, 6-pin SOT23 (DBV6), Green (RoHS & no Sb/Br)"
U5 U6: "ESD in 0402 Package with 10 pF Capacitance and 6 V Breakdown, 1 Channel, -40 to +125 degC, 2-pin X2SON (DPY), Green (RoHS & no Sb/Br)"
U7: "Mixed Signal Microcontroller, RGZ0048B"
U8: "Low Power, High Accuracy Digital Humidity Sensor with Temperature Sensor, YPA0008AGAE"
U9: library part OPT3001DNP, "Ambient Light Sensor, DNP0006A"
U10: "Multi-Channel 12/26-Bit Capacitance to Digital Converter (FDC) for Capacitive Sensing, DNT0012B"
Y1: "Crystal, 8MHz, 5pF, SMD"
Y2: "OSC, 40 MHz, 1.6 to 3.63 V, SMD"
ZZ1 ZZ2 ZZ3: library part AssemblyNote
ZZ4: library part "Assembly Note", "This Assembly Note will show in the PcbDoc and associated outputs"
ZZ5: library part AssemblyNote, "Component BL1 must be assembled to U5 Before U5 is attached to the board."
ZZ6: library part AssemblyNote, "Remove protective coverings from BL1 and U5"
ZZ7: library part AssemblyNote, "Slide pins of U5 into holes of BL1. BL1 must lie flat on the back of U5."
ZZ8: library part AssemblyNote, "Solder U5 - BL1 assembly to the board."
ZZ9: library part AssemblyNote, "Solder Pins 1, 2, 3, 18, 19, and 20 of U5 to BL1 from the top to insure electrical continuity."

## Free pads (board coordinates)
  round 60 hole 96 unplated: 0(2101.38,2920.08) 0(2898.62,2920.08)

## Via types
v1: diameter 20, hole 10, Layer 1 - Top Layer to Layer 4 - Bottom Layer, tented both sides, 171 vias
v2: diameter 19.68, hole 7.87, Layer 1 - Top Layer to Layer 4 - Bottom Layer, tented both sides, 14 vias

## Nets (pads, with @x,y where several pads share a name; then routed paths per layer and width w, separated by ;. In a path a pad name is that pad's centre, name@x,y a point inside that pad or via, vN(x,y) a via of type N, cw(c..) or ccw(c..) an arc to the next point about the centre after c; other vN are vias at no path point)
3P3V: C6.1 C7.1 C20.2 C21.2 C22.1 C29.1 D3.2 D4.2 J3.2 J6.2 L4.1 L5.1 L6.2 R16.2 R17.2 R18.2 R19.2 R20.2 R22.2 R25.2 TP3.1 U3.34 U3.35 U4.1 U7.37 U9.1 | length 9402.4
  Layer 1 - Top Layer w25: v1(2425,2951.5) U9.1@2461.69,2951.5
  Layer 3 - PWR w30: v1(1339.69,1871.81) 1339.69,1768.11 1360.5,1747.3 v1(1378.38,1747.3) 1402.7,1747.3 1425,1725 1425,1650 1325,1550 v1(1325,1540) 1325,1445 1435,1335 1850,1335 v1(1870,1355) 1885,1370 1885,1550 1960,1625 2580,1625 2610,1595 v1(2610,1555) v1(2610,1525) v1(2610,1495) 2630,1475 2840,1475 2866.2,1501.2 2866.2,1625 2901.2,1660 ; U3.35@2050,2745 U3.34@2125,2745 ; v1(2125,2655) v1(2125,2690) U3.34@2125,2745 ; v1(2425,2951.5) 2389.82,2951.5 2359,2920.68 2359,2841 ; v1(2495,2400) v1(2545,2400) 2550,2395 2550,2145.9 2590.9,2105 v1(2680,2105) v1(2730,2105) v1(2780,2105) v1(2830,2105) 2870,2065 v1(2870,1705) 2870,1691.2 2901.2,1660 ; v1(3535,1045) 3580,1000 3715,1000 v1(3785,1070) 3785,1540 v1(3805,1540) ; J3.2@3740,1595 3740,1605 3675,1670 3290,1670 3250,1630 3135,1630 3105,1660 2901.2,1660 ; v1(3805,1630) 3805,1820 3785,1840 v1(3785,2565) 3530,2820 2790,2820 2730,2880 v1(2651.38,2880) 2581.38,2810 2390,2810 2359,2841 ; U3.34@2125,2745 U3.34@2150,2745 2215,2810 2328.01,2810 2359,2841
  Layer 4 - Bottom Layer w10: U4.1@2032.66,2487.13 2032.66,2553.61 L4.1@2046.3,2567.25
  Layer 4 - Bottom Layer w12: C7.1@1975,2570.5 1978.24,2567.25 L4.1@2046.3,2567.25
  Layer 4 - Bottom Layer w20: R18.2@1338.62,1747.3 v1(1378.38,1747.3) ; J6.2@1339.69,1813.66 v1(1339.69,1871.81) ; v1(1870,1355) R25.2@1906.38,1355 ; R17.2@2495,2353.62 v1(2495,2400) ; R16.2@2545,2353.62 v1(2545,2400) ; R22.2@2610,2880 v1(2651.38,2880) ; v1(3535,1045) D4.2@3567.28,1045 ; v1(3785,1070) R20.2@3785,1111.38 ; R19.2@3785,2523.62 v1(3785,2565)
  Layer 4 - Bottom Layer w25: C29.1@2380,2951.5 v1(2425,2951.5) ; v1(2870,1705) L5.1@2870,1768.5
  Layer 4 - Bottom Layer w30: 1970,2617 2050,2697 U3.35@2050,2745
  other v1: 3805,1570 3805,1600
A0_SCLK: R13.2 U3.37 U7.11 | length 2109.6
  Layer 1 - Top Layer w10: U3.37@1850,2745 1770,2665 1510,2665 1455,2610 v1(1455,2155) 1455,2130 1770,1815 v1(1855,1815)
  Layer 4 - Bottom Layer w10: v1(1455,2155) R13.2@1455,2201.38 ; v1(1855,1815) 2390,1815 2411.42,1836.42 U7.11@2411.42,1866.14 U7.11@2411.42,1873
A0_SIMO: R14.2 U3.36 U7.24 | length 1876.7
  Layer 1 - Top Layer w10: U3.36@1950,2745 1845,2640 1545,2640 1510,2605 v1(1510,2155) 1545,2120 v1(2310,2120)
  Layer 4 - Bottom Layer w10: v1(1510,2155) R14.2@1510,2201.38 ; v1(2310,2120) 2321.73,2108.27 U7.24@2366.14,2108.27 U7.24@2373,2108.27
A0_SOMI: R15.1 U7.25 | length 922.5
  Layer 1 - Top Layer w10: v1(1565,2155) 2290,2155 v1(2310,2175)
  Layer 4 - Bottom Layer w10: v1(1565,2155) R15.1@1565,2201.38 ; v1(2310,2175) 2380,2175 2391.73,2163.27 U7.25@2391.73,2133.86 U7.25@2391.73,2127
A1_RX: R3.1 R6.1 U7.21 | length 2784.6
  Layer 1 - Top Layer w10: v1(1390,2640) 1375,2625 1375,2105 1428.62,2051.38 v1(1428.62,2033.62)
  Layer 4 - Bottom Layer w10: R6.1@1300,2673.62 1301.38,2675 1355,2675 v1(1390,2640) ; v1(1428.62,2033.62) R3.1@1390,2033.62 1193.62,2033.62 1140,1980 1140,1895 1180,1855 1180,1650 1215,1615 1520,1615 1954.21,2049.21 U7.21@2366.14,2049.21 U7.21@2373,2049.21
A1_TX: R4.1 R9.1 U7.20 | length 2562.9
  Layer 1 - Top Layer w10: v1(1190,2250) 1190,2660 v1(1205,2675)
  Layer 4 - Bottom Layer w10: v1(1190,2250) 1190,2070 1091.07,1971.07 R9.1@1091.07,1746.81 1091.07,1708.93 1205,1595 1530,1595 1964.53,2029.53 U7.20@2366.14,2029.53 U7.20@2373,2029.53 ; v1(1205,2675) 1243.62,2675 R4.1@1245,2673.62
AVCC: C17.2 C18.2 C19.1 L5.2 U7.48
AVCC_FLT: C28.2 C30.1 C31.2 C33.1 L6.1 R23.2 U8.B1 U10.7 | length 4144
  Layer 3 - PWR w30: v1(1335,2880) 1390,2880 1410,2860 1410,2720 1330,2640 1065,2640 1045,2620 v1(1045,2585) 1045,2565 1105,2505 1105,1210 1195,1120 1960,1120 2015,1175 2015,1270 1945,1340 1945,1530 1980,1565 v1(2340,1565) v1(2370,1565) v1(2400,1565) v1(2430,1565) v1(2460,1565) v1(2490,1565) v1(2520,1565)
  Layer 4 - Bottom Layer w10: U8.B1@1244.68,2869.85 1286.22,2869.85 C28.2@1295,2878.63
  Layer 4 - Bottom Layer w20: v1(1045,2585) R23.2@1045,2626.38 ; C28.2@1295,2878.63 1296.37,2880 v1(1335,2880)
B0_SCL: R16.1 TP5.1 U7.32 U8.A1 U9.4 U10.1 | length 5934.8
  Layer 1 - Top Layer w10: U9.4@2537.4,2899.41 v1(2537.4,2862.4) 2500,2825 2500,2651.46 2400,2551.46 2400,2375 2440,2335 v1(2616,2335) 2835,2335 3095,2075 3095,1705 v1(3005,1615)
  Layer 4 - Bottom Layer w10: U8.A1@1244.68,2889.53 1265.15,2910 1440,2910 1540,2810 1760,2810 TP5.1@1860,2910 1960,2810 2485,2810 v1(2537.4,2862.4) ; U10.1@2160,1350.79 U10.1@2150.2,1350.79 2120.79,1350.79 2100,1330 2100,1225 2025,1150 1765,1150 1725,1190 1725,1600 1765,1640 2615,1640 2640,1615 v1(3005,1615) ; U7.32@2529.53,2127 U7.32@2529.53,2133.86 2529.53,2249.53 2545,2265 R16.1@2545,2306.38 2603.38,2306.38 2615,2318 v1@2615,2334
B0_SDA: R17.1 TP6.1 U7.31 U8.A2 U9.6 U10.2 | length 6427
  Layer 1 - Top Layer w10: v1(1075,2890) 1065,2890 1045,2870 1045,2770 1095,2720 1370,2720 1555,2905 TP6.1@1650,2905 ; TP6.1@1650,2910 1750,2810 2200,2810 2370,2980 2525,2980 2537.4,2967.6 U9.6@2537.4,2950.59 2584.41,2950.59 2600,2935 2600,2711.46 2425,2536.46 2425,2390 v1(2450,2365) 2835,2365 3120,2080 3120,1680 v1(3055,1615)
  Layer 4 - Bottom Layer w10: v1(1075,2890) 1204.85,2890 U8.A2@1205.31,2889.53 ; U10.2@2160,1370.47 U10.2@2150.2,1370.47 2070.47,1370.47 1925,1225 1790,1225 1750,1265 1750,1585 1780,1615 2605,1615 2635,1585 3025,1585 v1(3055,1615) ; v1(2450,2365) 2450,2316 2459.62,2306.38 R17.1@2495,2306.38 2495,2265 2509.84,2250.16 U7.31@2509.84,2133.86 U7.31@2509.84,2127
BL_PWM: U4.2 U7.26 | length 590.9
  Layer 1 - Top Layer w10: v1@2071.06,2438 2199,2438 2220,2417 2220,2338 v1(2358,2200)
  Layer 4 - Bottom Layer w10: v1(2070.06,2439) U4.2@2070.06,2487.13 ; v1(2358,2200) 2385,2200 2411.42,2173.58 U7.26@2411.42,2133.86 U7.26@2411.42,2127
EM_CTS: J4.18 R2.1 | length 103.9
  Layer 4 - Bottom Layer w10: J4.18@1150,2522.52 R2.1@1150,2626.38
EM_RTS: J5.3 R10.2 | length 577.1
  Layer 4 - Bottom Layer w10: J5.3@1500,1187.48 1500,1115 1510,1105 1665,1105 1675,1115 R10.2@1675,1436.38
EM_RX: J4.14 R4.2 | length 103.9
  Layer 4 - Bottom Layer w10: J4.14@1250,2522.52 R4.2@1250,2626.38
EM_TX: J4.12 R6.2 | length 103.9
  Layer 4 - Bottom Layer w10: J4.12@1300,2522.52 R6.2@1300,2626.38
FDC_INTB: U7.18 U10.5 | length 1403.1
  Layer 1 - Top Layer w10: v1(1780,1560) 1765,1575 1765,1670 1945,1850 1945,1965 v1(1960,1980)
  Layer 4 - Bottom Layer w8: v1(1780,1560) 2105,1560 2123,1542 2123,1437 2130.47,1429.53 U10.5@2150.2,1429.53
  Layer 4 - Bottom Layer w10: v1(1960,1980) 2280,1980 2290.16,1990.16 U7.18@2366.14,1990.16
FDC_SD: U7.19 U10.6 | length 1338.1
  Layer 1 - Top Layer w10: v1(1810,1585) 1785,1610 1785,1655 2005,1875 2005,1990 v1(2020,2005)
  Layer 4 - Bottom Layer w8: v1(1810,1585) 2115,1585 2150.2,1549.8 U10.6@2150.2,1449.21
  Layer 4 - Bottom Layer w10: v1(2020,2005) 2024.84,2009.84 U7.19@2366.14,2009.84 U7.19@2373,2009.84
